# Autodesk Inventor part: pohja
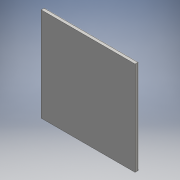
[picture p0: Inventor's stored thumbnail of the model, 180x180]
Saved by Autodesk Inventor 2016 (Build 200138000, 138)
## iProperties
Created: 2016-02
Part Number: pohja
Material: Generic
Document SubType Name: Modeling
Designer: Juha-Pekka
Density: 1 g/cm^3
Appearance: Default
Author: Juha-Pekka
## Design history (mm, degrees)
sketch "Sketch1"
  geometry: L1 (0, 0)-(200, 0); L2 (200, 0)-(200, -200); L3 (200, -200)-(0, -200); L4 (0, -200)-(0, 0)
  constraints: 8 end point, 2 parallel, 1 horizontal, 1 perpendicular
  dimensions: "d0" = 200 distance of L2.end L3.end; "d1" = 200 distance of L1.end L2.end
extrude "Extrusion1" new body sketch "Sketch1" distance "d2" = 8; taper "d3" = 0 deg
fillet "Fillet1" dims "d4" = 2
body "Solid1"
